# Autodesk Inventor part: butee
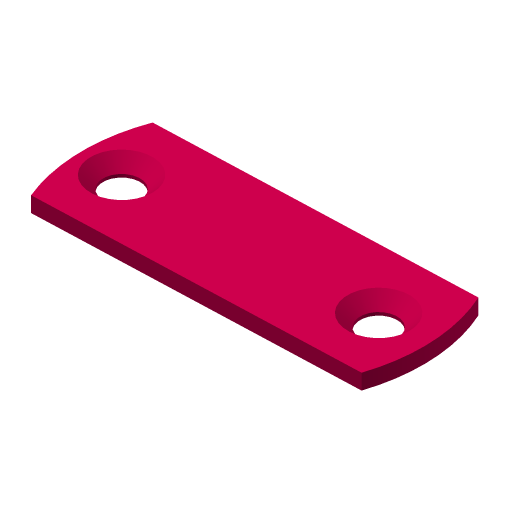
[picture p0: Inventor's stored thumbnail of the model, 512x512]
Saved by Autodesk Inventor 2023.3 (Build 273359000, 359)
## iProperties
Created: 2002-04
Part Number: butee
Material: Générique
Document SubType Name: Modélisation
Designer: Administrateur
Density: 1 g/cm^3
Appearance: Par défaut(1)
Control State: 0
Master: False
Checked Out: False
Shininess: 20.0
Angle Display Precision: 2
Document Length Units: 11269
Document Angle Units: 11279
Document Time Units: 11290
Document Mass Units: 11283
Document Length Units Precision: 3
Document Angle Units Precision: 2
Density: 0.0
Volumn: 0.0
Area: 0.0
PropertySet Name: Model Information
Author: Administrateur
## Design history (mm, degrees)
sketch "Esquisse1"
  geometry: L1 (-50.866, -20.919)-(52.245, -17.19); L2 (-51.584, 19.081)-(50.071, 22.757); C1 r 55 at (0, 0) reference; C2 r 6 at (-41.96, -0.584) reference; C3 r 6 at (38.253, 2.317) reference; C4 r 6 at (-41.96, -0.584); C5 r 6 at (38.253, 2.317); A1 r 55 centre (0, 0) between (52.245, -17.19) and (-50.866, -20.919) reference; A2 r 55 centre (0, 0) between (52.245, -17.19) and (50.071, 22.757); A3 r 55 centre (0, 0) between (-51.584, 19.081) and (-50.866, -20.919)
  constraints: 8 point on circle, 4 centre point, 4 end point, 3 coincident, 2 concentric
extrude "Extrusion1" new body sketch "Esquisse1" distance "d2" = 5; taper "d3" = 0 deg
sketch "Esquisse2"
  geometry: C1 r 6 at (-41.96, -0.584) reference; C2 r 6 at (38.253, 2.317) reference; 3 further points
  constraints: 2 coincident
hole "Perçage1" sketch "Esquisse2" at (-41.96, -0.584), (38.253, 2.317) diameter "d4" = 12; stored, may be unused: countersink angle "d8" = 90 deg, drill point angle "d10" = 118 deg; dims "d5" = 6, "d6" = 20, "d7" = 2, "d9" = 8
node "Solide1"
node "Corps solides"
node "Corps surfaciques"
node "Référence1"
node "Référence2"
node "Référence3"
node "Référence4"
